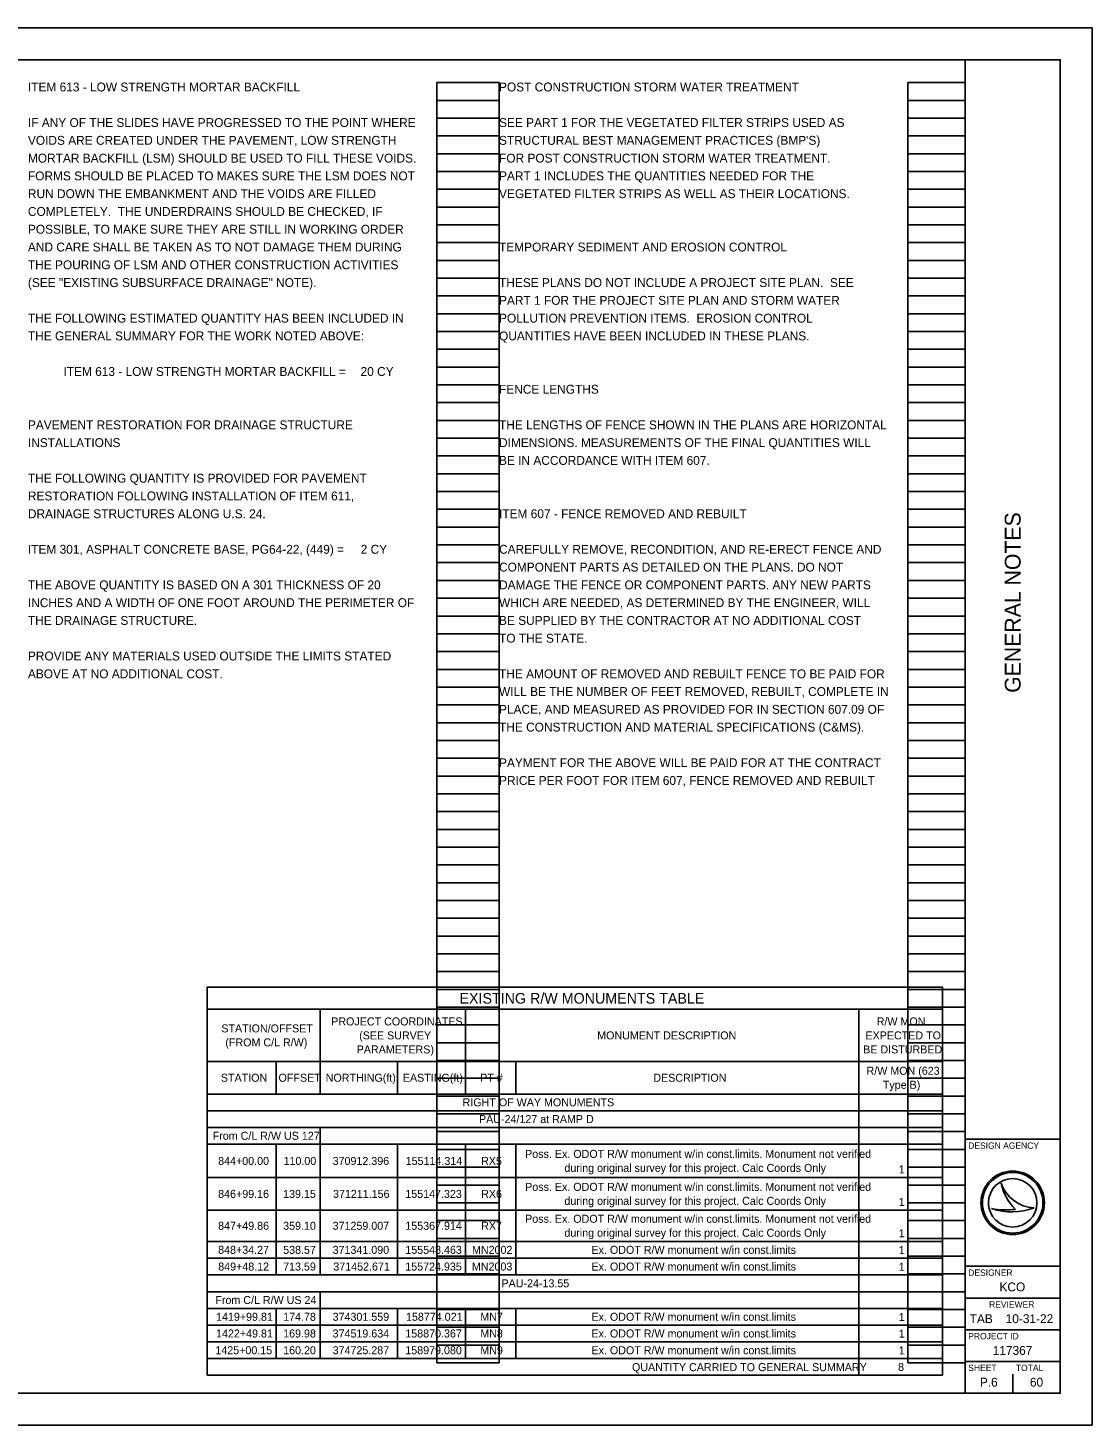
# Model space of a CAD drawing. Extents: x 0 to 42.9, y 0 to 22.
# Drawn here: x 17.24 to 34, y 0 to 22 of the extents above; entities that cross this region are included whole.
import ezdxf

# ---------------------------------------------------------------- set-up
doc = ezdxf.new("R2010")
doc.units = 0
for name, color, linetype in [('SH_Border', 7, 'Continuous'), ('SH_Cut_Line', 7, 'Continuous'), ('SH_Data', 7, 'Continuous'), ('SH_Text', 7, 'Continuous')]:
    doc.layers.add(name, color=color, linetype=linetype)

msp = doc.modelspace()

# ---------------------------------------------------------------- linework, layer by layer
at = {"layer": 'SH_Border'}
for p, q in [((32, 0.5), (32, 21.5)), ((32, 4.5), (33.5, 4.5)), ((32, 2.5), (33.5, 2.5)), ((32, 2), (33.5, 2)), ((32, 1.5), (33.5, 1.5)), ((32, 1), (33.5, 1))]:
    msp.add_line(p, q, dxfattribs=at)
msp.add_lwpolyline([(1.5, 21.5), (33.5, 21.5), (33.5, 0.5), (1.5, 0.5)], close=True, dxfattribs=at)
at = {"layer": 'SH_Cut_Line'}
msp.add_lwpolyline([(0, 0), (34, 0), (34, 22), (0, 22)], close=True, dxfattribs=at)
at = {"layer": 'SH_Data'}
for p, q in [((23.68, 0.98), (23.68, 21.14)), ((23.68, 21.14), (24.66, 21.14)), ((24.66, 0.98), (24.66, 21.14)), ((31.1, 0.98), (31.1, 21.14)), ((31.1, 21.14), (32, 21.14)), ((32, 0.98), (32, 21.14)), ((23.68, 20.86), (24.66, 20.86)), ((31.1, 20.86), (32, 20.86)), ((23.68, 20.58), (24.66, 20.58)), ((31.1, 20.58), (32, 20.58)), ((23.68, 20.3), (24.66, 20.3)), ((31.1, 20.3), (32, 20.3)), ((23.68, 20.02), (24.66, 20.02)), ((31.1, 20.02), (32, 20.02)), ((23.68, 19.74), (24.66, 19.74)), ((31.1, 19.74), (32, 19.74)), ((23.68, 19.46), (24.66, 19.46)), ((31.1, 19.46), (32, 19.46)), ((23.68, 19.18), (24.66, 19.18)), ((31.1, 19.18), (32, 19.18)), ((23.68, 18.9), (24.66, 18.9)), ((31.1, 18.9), (32, 18.9)), ((23.68, 18.62), (24.66, 18.62)), ((31.1, 18.62), (32, 18.62)), ((23.68, 18.34), (24.66, 18.34)), ((31.1, 18.34), (32, 18.34)), ((23.68, 18.06), (24.66, 18.06)), ((31.1, 18.06), (32, 18.06)), ((23.68, 17.78), (24.66, 17.78)), ((31.1, 17.78), (32, 17.78)), ((23.68, 17.5), (24.66, 17.5)), ((31.1, 17.5), (32, 17.5)), ((23.68, 17.22), (24.66, 17.22)), ((31.1, 17.22), (32, 17.22)), ((23.68, 16.94), (24.66, 16.94)), ((31.1, 16.94), (32, 16.94)), ((23.68, 16.66), (24.66, 16.66)), ((31.1, 16.66), (32, 16.66)), ((23.68, 16.38), (24.66, 16.38)), ((31.1, 16.38), (32, 16.38)), ((23.68, 16.1), (24.66, 16.1)), ((31.1, 16.1), (32, 16.1)), ((23.68, 15.82), (24.66, 15.82)), ((31.1, 15.82), (32, 15.82)), ((23.68, 15.54), (24.66, 15.54)), ((31.1, 15.54), (32, 15.54)), ((23.68, 15.26), (24.66, 15.26)), ((31.1, 15.26), (32, 15.26)), ((23.68, 14.98), (24.66, 14.98)), ((31.1, 14.98), (32, 14.98)), ((23.68, 14.7), (24.66, 14.7)), ((31.1, 14.7), (32, 14.7)), ((23.68, 14.42), (24.66, 14.42)), ((31.1, 14.42), (32, 14.42)), ((23.68, 14.14), (24.66, 14.14)), ((31.1, 14.14), (32, 14.14)), ((23.68, 13.86), (24.66, 13.86)), ((31.1, 13.86), (32, 13.86)), ((23.68, 13.58), (24.66, 13.58)), ((31.1, 13.58), (32, 13.58)), ((23.68, 13.3), (24.66, 13.3)), ((31.1, 13.3), (32, 13.3)), ((23.68, 13.02), (24.66, 13.02)), ((31.1, 13.02), (32, 13.02)), ((23.68, 12.74), (24.66, 12.74)), ((31.1, 12.74), (32, 12.74)), ((23.68, 12.46), (24.66, 12.46)), ((31.1, 12.46), (32, 12.46)), ((23.68, 12.18), (24.66, 12.18)), ((31.1, 12.18), (32, 12.18)), ((23.68, 11.9), (24.66, 11.9)), ((31.1, 11.9), (32, 11.9)), ((23.68, 11.62), (24.66, 11.62)), ((31.1, 11.62), (32, 11.62)), ((23.68, 11.34), (24.66, 11.34)), ((31.1, 11.34), (32, 11.34)), ((23.68, 11.06), (24.66, 11.06)), ((31.1, 11.06), (32, 11.06)), ((23.68, 10.78), (24.66, 10.78)), ((31.1, 10.78), (32, 10.78)), ((23.68, 10.5), (24.66, 10.5)), ((31.1, 10.5), (32, 10.5)), ((23.68, 10.22), (24.66, 10.22)), ((31.1, 10.22), (32, 10.22)), ((23.68, 9.94), (24.66, 9.94)), ((31.1, 9.94), (32, 9.94)), ((23.68, 9.66), (24.66, 9.66)), ((31.1, 9.66), (32, 9.66)), ((23.68, 9.38), (24.66, 9.38)), ((31.1, 9.38), (32, 9.38)), ((23.68, 9.1), (24.66, 9.1)), ((31.1, 9.1), (32, 9.1)), ((23.68, 8.82), (24.66, 8.82)), ((31.1, 8.82), (32, 8.82)), ((23.68, 8.54), (24.66, 8.54)), ((31.1, 8.54), (32, 8.54)), ((23.68, 8.26), (24.66, 8.26)), ((31.1, 8.26), (32, 8.26)), ((23.68, 7.98), (24.66, 7.98)), ((31.1, 7.98), (32, 7.98)), ((23.68, 7.7), (24.66, 7.7)), ((31.1, 7.7), (32, 7.7)), ((23.68, 7.42), (24.66, 7.42)), ((31.1, 7.42), (32, 7.42)), ((23.68, 7.14), (24.66, 7.14)), ((31.1, 7.14), (32, 7.14)), ((23.68, 6.86), (24.66, 6.86)), ((31.1, 6.86), (32, 6.86)), ((23.68, 6.58), (24.66, 6.58)), ((31.1, 6.58), (32, 6.58)), ((23.68, 6.3), (24.66, 6.3)), ((31.1, 6.3), (32, 6.3)), ((23.68, 6.02), (24.66, 6.02)), ((31.1, 6.02), (32, 6.02)), ((23.68, 5.74), (24.66, 5.74)), ((31.1, 5.74), (32, 5.74)), ((23.68, 5.46), (24.66, 5.46)), ((31.1, 5.46), (32, 5.46)), ((23.68, 5.18), (24.66, 5.18)), ((31.1, 5.18), (32, 5.18)), ((23.68, 4.9), (24.66, 4.9)), ((31.1, 4.9), (32, 4.9)), ((23.68, 4.62), (24.66, 4.62)), ((31.1, 4.62), (32, 4.62)), ((23.68, 4.34), (24.66, 4.34)), ((31.1, 4.34), (32, 4.34)), ((23.68, 4.06), (24.66, 4.06)), ((31.1, 4.06), (32, 4.06)), ((23.68, 3.78), (24.66, 3.78)), ((31.1, 3.78), (32, 3.78)), ((32.567, 3.81), (32.567, 3.81)), ((23.68, 3.5), (24.66, 3.5)), ((31.1, 3.5), (32, 3.5)), ((32.417, 3.41), (32.417, 3.41)), ((32.75, 3.5), (32.75, 3.5)), ((33.087, 3.419), (33.087, 3.419)), ((23.68, 3.22), (24.66, 3.22)), ((31.1, 3.22), (32, 3.22)), ((23.68, 2.94), (24.66, 2.94)), ((31.1, 2.94), (32, 2.94)), ((23.68, 2.66), (24.66, 2.66)), ((31.1, 2.66), (32, 2.66)), ((23.68, 2.38), (24.66, 2.38)), ((31.1, 2.38), (32, 2.38)), ((23.68, 2.1), (24.66, 2.1)), ((31.1, 2.1), (32, 2.1)), ((23.68, 1.82), (24.66, 1.82)), ((31.1, 1.82), (32, 1.82)), ((23.68, 1.54), (24.66, 1.54)), ((31.1, 1.54), (32, 1.54)), ((23.68, 1.26), (24.66, 1.26)), ((31.1, 1.26), (32, 1.26)), ((23.68, 0.98), (24.66, 0.98)), ((31.1, 0.98), (32, 0.98)), ((32.375, 0.675), (32.375, 0.675)), ((32.75, 0.5), (32.75, 0.8))]:
    msp.add_line(p, q, dxfattribs=at)
for radius in [0.5, 0.477, 0.477, 0.382]:
    msp.add_circle((32.75, 3.5), radius, dxfattribs=at)
for centre, radius, start, end in [((33.116, 3.998), 0.58, 198.9257, 198.9319), ((33.347, 3.97), 0.796, 191.6379, 191.6421), ((33.116, 3.998), 0.58, 198.9319, 267.1657), ((33.347, 3.97), 0.796, 191.6421, 226.0947), ((32.739, 4.37), 1.013, 251.4576, 290.0832), ((32.648, 4.654), 1.266, 259.4964, 259.4995), ((32.739, 4.37), 1.013, 251.4527, 251.4576), ((32.648, 4.654), 1.266, 259.4995, 276.6672)]:
    msp.add_arc(centre, radius, start, end, dxfattribs=at)
at = {"layer": 'SH_Text'}
for p, q in [((20.065, 6.893), (31.644, 6.893)), ((20.065, 6.893), (20.065, 0.783)), ((31.644, 6.893), (31.644, 0.783)), ((20.065, 6.548), (31.644, 6.548)), ((21.844, 6.548), (21.844, 5.213)), ((24.134, 6.548), (24.134, 5.213)), ((30.327, 6.548), (30.327, 0.783)), ((20.065, 5.724), (31.644, 5.724)), ((21.152, 5.724), (21.152, 5.213)), ((23.063, 5.724), (23.063, 5.213)), ((24.924, 5.724), (24.924, 5.213)), ((20.065, 5.213), (31.644, 5.213)), ((20.065, 4.95), (30.327, 4.95)), ((30.327, 4.95), (31.644, 4.95)), ((20.065, 4.686), (31.644, 4.686)), ((21.844, 4.686), (21.844, 2.364)), ((20.065, 4.423), (31.644, 4.423)), ((21.152, 4.423), (21.152, 2.364)), ((23.063, 4.423), (23.063, 2.364)), ((24.134, 4.423), (24.134, 2.364)), ((24.924, 4.423), (24.924, 2.364)), ((20.065, 3.896), (31.644, 3.896)), ((20.065, 3.385), (31.644, 3.385)), ((20.065, 2.891), (31.644, 2.891)), ((20.065, 2.628), (31.644, 2.628)), ((20.065, 2.364), (31.644, 2.364)), ((20.065, 2.1), (31.644, 2.1)), ((21.844, 2.1), (21.844, 1.046)), ((20.065, 1.837), (31.644, 1.837)), ((21.152, 1.837), (21.152, 1.046)), ((23.063, 1.837), (23.063, 1.046)), ((24.134, 1.837), (24.134, 1.046)), ((24.924, 1.837), (24.924, 1.046)), ((20.065, 1.573), (31.644, 1.573)), ((20.065, 1.31), (31.644, 1.31)), ((20.065, 1.046), (31.644, 1.046)), ((20.065, 0.783), (31.644, 0.783))]:
    msp.add_line(p, q, dxfattribs=at)

# ---------------------------------------------------------------- texts
at = {"layer": 'SH_Data'}
msp.add_text('GENERAL NOTES', height=0.25, rotation=90, dxfattribs=at).set_placement((32.875, 11.531))
for s, height, p in [('DESIGN AGENCY', 0.1, (32.05, 4.35)), ('DESIGNER', 0.1, (32.05, 2.35)), ('KCO', 0.14, (32.542, 2.105)), ('REVIEWER', 0.1, (32.378, 1.85)), ('TAB', 0.14, (32.072, 1.605)), ('10-31-22', 0.14, (32.639, 1.605)), ('PROJECT ID', 0.1, (32.05, 1.35)), ('117367', 0.14, (32.435, 1.105)), ('SHEET', 0.1, (32.05, 0.85)), ('TOTAL', 0.1, (32.8, 0.85)), ('P.6', 0.14, (32.233, 0.605)), ('60', 0.14, (33.021, 0.605))]:
    msp.add_text(s, height=height, dxfattribs=at).set_placement(p)
at = {"layer": 'SH_Text'}
for s, height, p in [('ITEM 613 - LOW STRENGTH MORTAR BACKFILL', 0.14, (17.24, 21)), ('POST CONSTRUCTION STORM WATER TREATMENT', 0.14, (24.66, 21)), ('IF ANY OF THE SLIDES HAVE PROGRESSED TO THE POINT WHERE ', 0.14, (17.24, 20.44)), ('SEE PART 1 FOR THE VEGETATED FILTER STRIPS USED AS ', 0.14, (24.66, 20.44)), ('VOIDS ARE CREATED UNDER THE PAVEMENT, LOW STRENGTH ', 0.14, (17.24, 20.16)), ("STRUCTURAL BEST MANAGEMENT PRACTICES (BMP'S) ", 0.14, (24.66, 20.16)), ('MORTAR BACKFILL (LSM) SHOULD BE USED TO FILL THESE VOIDS.  ', 0.14, (17.24, 19.88)), ('FOR POST CONSTRUCTION STORM WATER TREATMENT.  ', 0.14, (24.66, 19.88)), ('FORMS SHOULD BE PLACED TO MAKES SURE THE LSM DOES NOT ', 0.14, (17.24, 19.6)), ('PART 1 INCLUDES THE QUANTITIES NEEDED FOR THE ', 0.14, (24.66, 19.6)), ('RUN DOWN THE EMBANKMENT AND THE VOIDS ARE FILLED ', 0.14, (17.24, 19.32)), ('VEGETATED FILTER STRIPS AS WELL AS THEIR LOCATIONS.', 0.14, (24.66, 19.32)), ('COMPLETELY.  THE UNDERDRAINS SHOULD BE CHECKED, IF ', 0.14, (17.24, 19.04)), ('POSSIBLE, TO MAKE SURE THEY ARE STILL IN WORKING ORDER ', 0.14, (17.24, 18.76)), ('AND CARE SHALL BE TAKEN AS TO NOT DAMAGE THEM DURING ', 0.14, (17.24, 18.48)), ('TEMPORARY SEDIMENT AND EROSION CONTROL', 0.14, (24.66, 18.48)), ('THE POURING OF LSM AND OTHER CONSTRUCTION ACTIVITIES ', 0.14, (17.24, 18.2)), ('(SEE "EXISTING SUBSURFACE DRAINAGE" NOTE).', 0.14, (17.24, 17.92)), ('THESE PLANS DO NOT INCLUDE A PROJECT SITE PLAN.  SEE ', 0.14, (24.66, 17.92)), ('PART 1 FOR THE PROJECT SITE PLAN AND STORM WATER ', 0.14, (24.66, 17.64)), ('THE FOLLOWING ESTIMATED QUANTITY HAS BEEN INCLUDED IN ', 0.14, (17.24, 17.36)), ('POLLUTION PREVENTION ITEMS.  EROSION CONTROL ', 0.14, (24.66, 17.36)), ('THE GENERAL SUMMARY FOR THE WORK NOTED ABOVE:', 0.14, (17.24, 17.08)), ('QUANTITIES HAVE BEEN INCLUDED IN THESE PLANS.', 0.14, (24.66, 17.08)), ('ITEM 613 - LOW STRENGTH MORTAR BACKFILL = ', 0.14, (17.8, 16.52)), ('20 CY', 0.14, (22.479, 16.52)), ('FENCE LENGTHS', 0.14, (24.66, 16.24)), ('PAVEMENT RESTORATION FOR DRAINAGE STRUCTURE', 0.14, (17.24, 15.68)), ('THE LENGTHS OF FENCE SHOWN IN THE PLANS ARE HORIZONTAL', 0.14, (24.66, 15.68)), ('INSTALLATIONS', 0.14, (17.24, 15.4)), ('DIMENSIONS. MEASUREMENTS OF THE FINAL QUANTITIES WILL', 0.14, (24.66, 15.4)), ('BE IN ACCORDANCE WITH ITEM 607.', 0.14, (24.66, 15.12)), ('THE FOLLOWING QUANTITY IS PROVIDED FOR PAVEMENT', 0.14, (17.24, 14.84)), ('RESTORATION FOLLOWING INSTALLATION OF ITEM 611,', 0.14, (17.24, 14.56)), ('DRAINAGE STRUCTURES ALONG U.S. 24.', 0.14, (17.24, 14.28)), ('ITEM 607 - FENCE REMOVED AND REBUILT', 0.14, (24.66, 14.28)), ('ITEM 301, ASPHALT CONCRETE BASE, PG64-22, (449) = ', 0.14, (17.24, 13.72)), ('2 CY', 0.14, (22.481, 13.72)), ('CAREFULLY REMOVE, RECONDITION, AND RE-ERECT FENCE AND', 0.14, (24.66, 13.72)), ('COMPONENT PARTS AS DETAILED ON THE PLANS. DO NOT', 0.14, (24.66, 13.44)), ('THE ABOVE QUANTITY IS BASED ON A 301 THICKNESS OF 20', 0.14, (17.24, 13.16)), ('DAMAGE THE FENCE OR COMPONENT PARTS. ANY NEW PARTS', 0.14, (24.66, 13.16)), ('INCHES AND A WIDTH OF ONE FOOT AROUND THE PERIMETER OF', 0.14, (17.24, 12.88)), ('WHICH ARE NEEDED, AS DETERMINED BY THE ENGINEER, WILL', 0.14, (24.66, 12.88)), ('THE DRAINAGE STRUCTURE.', 0.14, (17.24, 12.6)), ('BE SUPPLIED BY THE CONTRACTOR AT NO ADDITIONAL COST', 0.14, (24.66, 12.6)), ('TO THE STATE.', 0.14, (24.66, 12.32)), ('PROVIDE ANY MATERIALS USED OUTSIDE THE LIMITS STATED', 0.14, (17.24, 12.04)), ('ABOVE AT NO ADDITIONAL COST.', 0.14, (17.24, 11.76)), ('THE AMOUNT OF REMOVED AND REBUILT FENCE TO BE PAID FOR ', 0.14, (24.66, 11.76)), ('WILL BE THE NUMBER OF FEET REMOVED, REBUILT, COMPLETE IN ', 0.14, (24.66, 11.48)), ('PLACE, AND MEASURED AS PROVIDED FOR IN SECTION 607.09 OF ', 0.14, (24.66, 11.2)), ('THE CONSTRUCTION AND MATERIAL SPECIFICATIONS (C&MS).', 0.14, (24.66, 10.92)), ('PAYMENT FOR THE ABOVE WILL BE PAID FOR AT THE CONTRACT', 0.14, (24.66, 10.36)), ('PRICE PER FOOT FOR ITEM 607, FENCE REMOVED AND REBUILT', 0.14, (24.66, 10.08)), ('EXISTING R/W MONUMENTS TABLE', 0.168, (24.037, 6.636)), ('PROJECT COORDINATES       ', 0.126, (22.017, 6.293)), ('R/W MON. ', 0.126, (30.608, 6.293)), ('STATION/OFFSET ', 0.126, (20.286, 6.183)), ('(SEE SURVEY ', 0.126, (22.457, 6.073)), ('MONUMENT DESCRIPTION', 0.126, (26.206, 6.073)), ('EXPECTED TO ', 0.126, (30.431, 6.073)), ('(FROM C/L R/W)', 0.126, (20.349, 5.963)), ('PARAMETERS)', 0.126, (22.418, 5.852)), ('BE DISTURBED', 0.126, (30.395, 5.852)), ('STATION', 0.126, (20.279, 5.406)), ('OFFSET', 0.126, (21.187, 5.406)), ('NORTHING(ft)', 0.126, (21.93, 5.406)), ('EASTING(ft)', 0.126, (23.145, 5.406)), ('PT #', 0.126, (24.363, 5.406)), ('DESCRIPTION', 0.126, (27.09, 5.406)), ('R/W MON (623 ', 0.126, (30.448, 5.516)), ('Type B)', 0.126, (30.705, 5.295)), ('RIGHT OF WAY MONUMENTS', 0.126, (24.086, 5.019)), ('PAU-24/127 at RAMP D', 0.126, (24.344, 4.755)), ('From C/L R/W US 127', 0.126, (20.15, 4.492)), ('844+00.00', 0.126, (20.236, 4.096)), ('110.00', 0.126, (21.266, 4.096)), ('370912.396', 0.126, (22.039, 4.096)), ('155114.314', 0.126, (23.19, 4.096)), ('RX5', 0.126, (24.378, 4.096)), ('Poss. Ex. ODOT R/W monument w/in const.limits. Monument not verified ', 0.126, (25.071, 4.207)), ('during original survey for this project. Calc Coords Only', 0.126, (25.689, 3.986)), ('1', 0.126, (30.956, 3.962)), ('Poss. Ex. ODOT R/W monument w/in const.limits. Monument not verified ', 0.126, (25.071, 3.688)), ('846+99.16', 0.126, (20.236, 3.577)), ('139.15', 0.126, (21.259, 3.577)), ('371211.156', 0.126, (22.045, 3.577)), ('155147.323', 0.126, (23.184, 3.577)), ('RX6', 0.126, (24.378, 3.577)), ('during original survey for this project. Calc Coords Only', 0.126, (25.689, 3.467)), ('1', 0.126, (30.956, 3.451)), ('Poss. Ex. ODOT R/W monument w/in const.limits. Monument not verified ', 0.126, (25.071, 3.185)), ('847+49.86', 0.126, (20.236, 3.075)), ('359.10', 0.126, (21.26, 3.075)), ('371259.007', 0.126, (22.039, 3.075)), ('155367.914', 0.126, (23.184, 3.075)), ('RX7', 0.126, (24.378, 3.075)), ('during original survey for this project. Calc Coords Only', 0.126, (25.689, 2.965)), ('1', 0.126, (30.956, 2.957)), ('848+34.27', 0.126, (20.236, 2.696)), ('538.57', 0.126, (21.26, 2.696)), ('371341.090', 0.126, (22.039, 2.696)), ('155548.463', 0.126, (23.184, 2.696)), ('MN2002', 0.126, (24.234, 2.696)), ('Ex. ODOT R/W monument w/in const.limits', 0.126, (26.116, 2.696)), ('1', 0.126, (30.956, 2.693)), ('849+48.12', 0.126, (20.237, 2.433)), ('713.59', 0.126, (21.26, 2.433)), ('371452.671', 0.126, (22.05, 2.433)), ('155724.935', 0.126, (23.183, 2.433)), ('MN2003', 0.126, (24.233, 2.433)), ('Ex. ODOT R/W monument w/in const.limits', 0.126, (26.116, 2.433)), ('1', 0.126, (30.956, 2.43)), ('PAU-24-13.55', 0.126, (24.698, 2.169)), ('From C/L R/W US 24', 0.126, (20.192, 1.906)), ('1419+99.81', 0.126, (20.203, 1.642)), ('174.78', 0.126, (21.26, 1.642)), ('374301.559', 0.126, (22.039, 1.642)), ('158774.021', 0.126, (23.195, 1.642)), ('MN7', 0.126, (24.365, 1.642)), ('Ex. ODOT R/W monument w/in const.limits', 0.126, (26.116, 1.642)), ('1', 0.126, (30.956, 1.639)), ('1422+49.81', 0.126, (20.203, 1.379)), ('169.98', 0.126, (21.26, 1.379)), ('374519.634', 0.126, (22.039, 1.379)), ('158870.367', 0.126, (23.184, 1.379)), ('MN8', 0.126, (24.365, 1.379)), ('Ex. ODOT R/W monument w/in const.limits', 0.126, (26.116, 1.379)), ('1', 0.126, (30.956, 1.376)), ('1425+00.15', 0.126, (20.192, 1.115)), ('160.20', 0.126, (21.26, 1.115)), ('374725.287', 0.126, (22.039, 1.115)), ('158979.080', 0.126, (23.184, 1.115)), ('MN9', 0.126, (24.365, 1.115)), ('Ex. ODOT R/W monument w/in const.limits', 0.126, (26.116, 1.115)), ('1', 0.126, (30.956, 1.112)), ('QUANTITY CARRIED TO GENERAL SUMMARY', 0.126, (26.754, 0.849)), ('8', 0.126, (30.945, 0.852))]:
    msp.add_text(s, height=height, dxfattribs=at).set_placement(p)

doc.saveas('drawing.dxf')
